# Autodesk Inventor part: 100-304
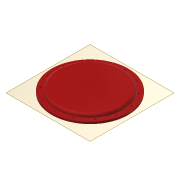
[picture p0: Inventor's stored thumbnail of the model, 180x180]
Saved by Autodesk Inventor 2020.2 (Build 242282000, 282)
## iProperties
Created: 2011-01
Part Number: 100-304
Document SubType Name: Modeling
Designer: F.Stasiak
Density: 1 g/cm^3
Material: Ogólny
Appearance: Gładkie — czerwone
Company: Fabian Stasiak CAD Consulting
Manager: www.cadconsulting.pl
Author: F.Stasiak
Subject: Zbiór ćwiczeń. Autodesk Inventor 2020. Kurs podstawowy
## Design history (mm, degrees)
sketch "Szkic1"
  geometry: C1 r 130 at (0, 0); 1 further point
  constraints: 1 centre point, 1 coincident
  dimensions: "d0" = 260 diameter of C1
node "Płaszczyzna konstrukcyjna1"
sketch "Szkic2"
  geometry: C1 r 3.324 at (59.659, 123.883) reference; C2 r 3.324 at (107.502, 85.73) reference; C3 r 3.323 at (134.053, 30.597) reference; C4 r 3.324 at (134.053, -30.597) reference; C5 r 3.323 at (107.502, -85.73) reference; C6 r 3.323 at (59.659, -123.883) reference; C7 r 3.324 at (0, -137.5) reference; C8 r 3.324 at (-59.659, -123.883) reference; C9 r 3.324 at (-107.502, -85.73) reference; C10 r 3.324 at (-134.053, -30.597) reference; C11 r 3.324 at (-134.053, 30.597) reference; C12 r 3.324 at (-107.502, 85.73) reference; C13 r 3.324 at (-59.659, 123.883) reference; C14 r 3.324 at (0, 137.5) reference; C15 r 125 at (0, 0) reference; C16 r 150 at (0, 0) reference; 1 further point
extrude "Wyciągnięcie proste1" new body sketch "Szkic2" distance "d1" = 8; taper "d2" = 0 deg
extrude "Wyciągnięcie proste2" join sketch "Szkic1" distance "d3" = 20; taper "d4" = 0 deg
fillet "Zaokrąglenie1" dims "d5" = 10
node "Bryła1"
node "Odniesienie1"
